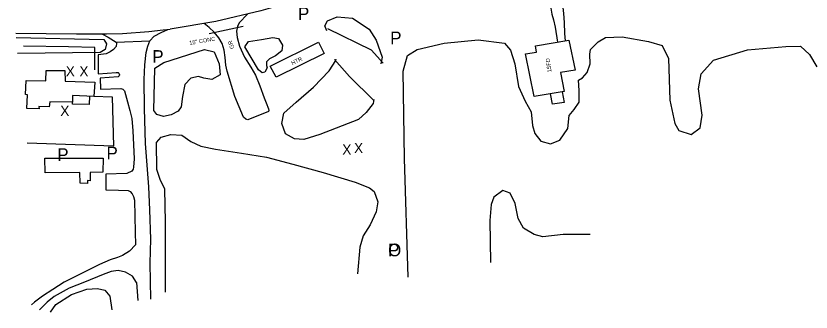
# Model space of a CAD drawing. Extents: x 2030130 to 2036320, y 723205 to 762423.
# Drawn here: x 2031864 to 2032648, y 738991 to 739283 of the extents above; entities that cross this region are included whole.
import ezdxf

# ---------------------------------------------------------------- set-up
doc = ezdxf.new("R2010")
doc.units = 0
for name, color, linetype in [('Draft_Station Cardinal Points', 7, 'Continuous'), ('Draft_Station Labels Major', 7, 'Continuous'), ('Draft_Station Tics Major', 7, 'Continuous'), ('Draft_Station Tics Minor', 7, 'Continuous'), ('Exist Terrain Model Ground Surface', 7, 'Continuous'), ('Old_Level_23', 7, 'Continuous'), ('Old_Level_26', 7, 'Continuous'), ('Old_Level_28', 7, 'Continuous'), ('Prop Horizontal Alignment Ramp', 7, 'Continuous')]:
    doc.layers.add(name, color=color, linetype=linetype)

msp = doc.modelspace()

# ---------------------------------------------------------------- linework, layer by layer
at = {"layer": 'Draft_Station Labels Major'}
for points in [[(2032501.35, 739404.8), (2032453.11, 739391.15), (2032410.68, 739378.56), (2032368.18, 739366.15), (2032325.83, 739353.7), (2032282.45, 739340.8), (2032239.49, 739328.13), (2032193.77, 739314.4), (2032149.21, 739301.07), (2032105.74, 739288.07), (2032061.22, 739277.6), (2032016.41, 739270.14)], [(2032395.37, 739374.09), (2032391, 739368.84), (2032390.01, 739363.89), (2032390.6, 739360.06), (2032392.28, 739351.4), (2032395.19, 739334.2), (2032398.05, 739320.73), (2032402.69, 739297.31), (2032403.83, 739285.39), (2032404.6, 739276.47), (2032405.01, 739265.88), (2032405.71, 739258.6)], [(2032367.63, 739365.99), (2032372.06, 739362.41), (2032375.31, 739359.03), (2032377.7, 739354.49), (2032379.62, 739349.87), (2032381.34, 739344.97), (2032383.76, 739333.66), (2032386.53, 739316.3), (2032388.71, 739302.76), (2032390.1, 739296.11), (2032391.46, 739290.87), (2032392.58, 739284.92), (2032394.01, 739279.2), (2032395.58, 739272.11), (2032398.05, 739257.33)], [(2032092.38, 739284.93), (2032084.38, 739276.17), (2032082.66, 739272.56), (2032081.76, 739268.15), (2032082.18, 739261.93), (2032084.7, 739253.19), (2032089.4, 739242.26), (2032095.86, 739232.53), (2032100.49, 739224.62), (2032104.66, 739214), (2032108.87, 739202.27), (2032110.83, 739197.27), (2032113.11, 739191.47), (2032113.38, 739189.75), (2032113.13, 739188.84), (2032092.81, 739180.45), (2032090.89, 739181.22), (2032088.66, 739183.28), (2032080.13, 739203.44), (2032072.32, 739228.45), (2032071.26, 739234.52), (2032070.53, 739242.04), (2032069.57, 739249.37), (2032067.46, 739256.04), (2032064.15, 739261.63), (2032059.68, 739267.07), (2032054.59, 739271.76), (2032049.88, 739275.71)], [(2031864.24, 739266.19), (2031923.81, 739265.48), (2031953.41, 739265.46), (2031969.19, 739265.78), (2031995.1, 739267.66), (2032009.5, 739269.27), (2032016.41, 739270.14)], [(2031948.98, 739265.46), (2031955.15, 739262.13), (2031963.1, 739257.15), (2031996.15, 739258.68), (2032000.54, 739263.25), (2032007.25, 739266.8), (2032013.99, 739269.84)], [(2031963.1, 739257.15), (2031963.3, 739256.11), (2031962.9, 739253.01), (2031960.49, 739249.84), (2031957.12, 739247.6), (2031953.18, 739245.75), (2031945.2, 739244.64), (2031945.48, 739225.89), (2031963.21, 739227.19), (2031965, 739227.28), (2031965.84, 739226.7), (2031966.28, 739225.05), (2031966.05, 739223.84), (2031965.08, 739222.96), (2031947.26, 739221.63), (2031947.49, 739210.97), (2031967.78, 739211.45), (2031969.63, 739210.86), (2031971.18, 739209.24), (2031974.39, 739198.23), (2031976.64, 739189.69), (2031978.6, 739181.84), (2031979.37, 739169.58), (2031980.8, 739141.96), (2031980.15, 739133.8), (2031979.72, 739131.8), (2031978.39, 739129.76), (2031973.72, 739127.72), (2031952.97, 739126.87), (2031952.86, 739111.42), (2031965.46, 739111.1), (2031974.95, 739110.67), (2031976.85, 739109.7), (2031978.98, 739107.39), (2031980.12, 739105), (2031981.03, 739101.4), (2031981.87, 739069.6), (2031982.03, 739057.22)], [(2031997.19, 739062.85), (2031996.18, 739091.74), (2031995.1, 739114.33), (2031992.08, 739157.34), (2031991.08, 739191.62), (2031990.55, 739220.3), (2031991.22, 739234.85), (2031992.61, 739247.05), (2031994.19, 739253.35), (2031996.15, 739258.68)], [(2031997.13, 739003.43), (2031996.65, 739039.22), (2031997.19, 739062.85)], [(2031982.03, 739057.22), (2031976.3, 739050.91), (2031969.41, 739046.78), (2031964.41, 739044.81), (2031957.1, 739042.25), (2031946.7, 739037.76), (2031927.6, 739028.32), (2031911.93, 739020.23), (2031900.74, 739013.1), (2031890.49, 739006.44), (2031882.64, 739000.61), (2031879.56, 738997.88)], [(2031983.15, 739019.91), (2031979.02, 739026.29), (2031972.42, 739030.19), (2031965.02, 739031.74), (2031957.99, 739030.8), (2031950.23, 739027.85), (2031931.89, 739020.34), (2031916.76, 739014.49), (2031901.85, 739006), (2031895.02, 739000.68), (2031887.56, 738993.08)], [(2031983.15, 739019.91), (2031984.27, 739002.12)]]:
    msp.add_lwpolyline(points, dxfattribs=at)
at = {"layer": 'Draft_Station Tics Major'}
for points in [[(2032170.6, 739268.5), (2032168.68, 739273.37), (2032171.41, 739278.3), (2032180.82, 739282.2), (2032196.12, 739280.91), (2032212.52, 739270.13), (2032219.42, 739259.27), (2032225.38, 739242.56), (2032224.03, 739235.75)], [(2032226.31, 739236.33), (2032214.71, 739249.21), (2032171.52, 739270.46)], [(2031864.47, 739261.67), (2031950.88, 739259.96), (2031953.38, 739255.67), (2031952.12, 739250.11), (2031947.27, 739246.98), (2031865.95, 739246.04)], [(2032103.48, 739229.91), (2032089.85, 739252.73), (2032093.46, 739257.99), (2032106.15, 739259.74), (2032117.51, 739261.77), (2032123.11, 739260.93), (2032127.1, 739254.39), (2032126.26, 739248.79), (2032120.2, 739243.58), (2032114.02, 739240.74), (2032111.13, 739237.78), (2032111.14, 739234.14), (2032112.04, 739231.86), (2032109.46, 739227.6), (2032107.11, 739226.88), (2032103.48, 739229.91)], [(2032250.76, 739025.35), (2032247.33, 739142.36), (2032246.07, 739228.6), (2032250.08, 739244.16), (2032259.75, 739249.99), (2032286.48, 739256.24), (2032319.7, 739259.36), (2032345.67, 739256.2), (2032351.59, 739249.4), (2032355.89, 739235.89), (2032359.46, 739213.38), (2032366.31, 739199.05), (2032372.13, 739188.37), (2032373.38, 739174.87), (2032375.82, 739167.12), (2032381.48, 739159.41), (2032391.17, 739156.94), (2032400.3, 739160.53), (2032408.11, 739172.11), (2032409.66, 739184.67), (2032414.42, 739190.6), (2032419.41, 739198.03), (2032419.33, 739209.55), (2032418.8, 739219.68), (2032422.56, 739221.97), (2032427.43, 739227.12), (2032430.07, 739235.86), (2032429.99, 739245.36), (2032430.65, 739249.87), (2032438.12, 739257.67), (2032445.43, 739261.76), (2032461.76, 739262.5)], [(2032461.76, 739262.5), (2032487.84, 739257.96), (2032501.1, 739253.86), (2032507.48, 739241.06), (2032508.59, 739199.88), (2032513.68, 739176.93), (2032517.51, 739170.17), (2032529.76, 739166.08), (2032538.8, 739172.81), (2032540.7, 739185.01), (2032536.93, 739211.29), (2032539.72, 739225.84), (2032551.76, 739239.36), (2032585.2, 739249.53), (2032623.06, 739252.98), (2032637.47, 739253.15), (2032646.4, 739245.16), (2032653.59, 739232.87)], [(2032000.05, 739189.87), (2032001.14, 739231.44), (2032010.04, 739237.16), (2032050.05, 739249.85), (2032059.77, 739247.79), (2032064.64, 739235.93), (2032065.45, 739225.1), (2032057.4, 739220.31), (2032049.56, 739221.69), (2032044.11, 739223.19), (2032036.6, 739221.66), (2032030.89, 739215.57), (2032028.54, 739203.5), (2032027.04, 739193.38), (2032024.29, 739189.06), (2032017.43, 739185.35), (2032009.68, 739183.93), (2032003.08, 739185.79), (2032000.05, 739189.87)], [(2032163.66, 739166.01), (2032148.15, 739161.13), (2032138.97, 739161.78), (2032129.93, 739166.74), (2032126.35, 739176.88), (2032128.44, 739187.03), (2032140.35, 739197.99), (2032157.49, 739212.63), (2032172.83, 739228.79), (2032179.51, 739239.12), (2032179.78, 739240.41)], [(2032178.13, 739240.03), (2032192.95, 739223.28), (2032216.64, 739200.09)], [(2032217.05, 739200.5), (2032216.28, 739196.62), (2032209.57, 739187.91), (2032202, 739180.88), (2032163.66, 739166.01)], [(2032011.52, 739010.37), (2032011.55, 739079.9), (2032011.11, 739111.95), (2032006.54, 739121.51), (2032003.21, 739131.54), (2032002.7, 739158.1), (2032007.5, 739163.43), (2032017.04, 739165.96), (2032027.76, 739165.51), (2032036.58, 739159.05), (2032046.6, 739154.68), (2032061.05, 739151.44), (2032086.63, 739147.71), (2032111.16, 739143.57), (2032137.08, 739136.94), (2032167.15, 739128.49), (2032198.48, 739118.91), (2032212.8, 739113.4), (2032217.47, 739109.76), (2032221.06, 739099.62), (2032219.31, 739089.61), (2032213.42, 739076.76), (2032206.53, 739065.94), (2032203.17, 739054.89), (2032200.8, 739028.43)], [(2032430.07, 739067.24), (2032403.49, 739067.33), (2032383.54, 739064.97), (2032374.87, 739067.44), (2032364.51, 739073.7), (2032359.17, 739083.15), (2032356.25, 739097.81), (2032351.33, 739108.24), (2032344.27, 739110.74), (2032335.23, 739104.35), (2032332.63, 739097.04), (2032331.21, 739081.08), (2032332.01, 739039.85)], [(2031898.19, 738990.74), (2031903.7, 738998.38), (2031919.14, 739008.1), (2031934.02, 739013.54), (2031944.5, 739014.22), (2031951.88, 739012.46), (2031956.93, 739006.33), (2031958.77, 738992.87)]]:
    msp.add_lwpolyline(points, dxfattribs=at)
at = {"layer": 'Draft_Station Tics Minor'}
msp.add_lwpolyline([(2032088.26, 739272.68), (2032054.79, 739265.51)], dxfattribs=at)
at = {"layer": 'Exist Terrain Model Ground Surface'}
for points in [[(2032168.04, 739246.15), (2032120.7, 739222.68), (2032114.93, 739233.49), (2032162.62, 739257.09)], [(2032415.34, 739229.53), (2032401.03, 739227.25), (2032404.53, 739208.55), (2032375.03, 739203.65), (2032366.42, 739245.68), (2032377.36, 739247.24), (2032376.24, 739253.7), (2032409.35, 739259.21)], [(2031874.31, 739219.52), (2031893.72, 739219.14), (2031894.12, 739229.23), (2031912.62, 739229.1), (2031912.83, 739218.75), (2031942.14, 739217.69), (2031941.14, 739203.72), (2031920.16, 739204.49), (2031919.91, 739197.91), (2031897.63, 739198.37), (2031897.14, 739193.42), (2031886.96, 739193.78), (2031887.18, 739191.43), (2031875.09, 739191.75), (2031875.58, 739205.22), (2031873.62, 739205.56)], [(2031892.79, 739142.85), (2031950.13, 739142.68), (2031949.99, 739128.84), (2031937.47, 739128.48), (2031937.47, 739120.47), (2031934.69, 739120.59), (2031934.95, 739117.86), (2031927.71, 739117.95), (2031927.34, 739128.45), (2031892.93, 739128.31)]]:
    msp.add_lwpolyline(points, close=True, dxfattribs=at)
for points in [[(2031942.14, 739229.77), (2031942.14, 739251.97), (2031916.11, 739252.69), (2031871.84, 739253.13)], [(2031941.16, 739203.91), (2031959.22, 739203.34), (2031960.36, 739154.53), (2031875.4, 739157.42)], [(2031936.67, 739203.88), (2031936.52, 739195.62), (2031919.92, 739196.09), (2031919.91, 739197.91)], [(2032402.76, 739208.26), (2032404.74, 739197.69), (2032393.19, 739195.88), (2032391.09, 739206.32)]]:
    msp.add_lwpolyline(points, dxfattribs=at)

# ---------------------------------------------------------------- texts
at = {"layer": 'Draft_Station Cardinal Points'}
msp.add_text('O', height=12.5, dxfattribs=at).set_placement((2032231.06, 739045.83))
at = {"layer": 'Draft_Station Tics Major'}
for p in [(2031913.43, 739223.44), (2031926.82, 739223.43), (2031907.99, 739184.41), (2032185.96, 739146.21), (2032197.53, 739147.71)]:
    msp.add_text('X', height=10, dxfattribs=at).set_placement(p)
at = {"layer": 'Old_Level_23'}
msp.add_text('GR', height=4, rotation=107.88847, dxfattribs=at).set_placement((2032079.53, 739251.28))
at = {"layer": 'Old_Level_26'}
msp.add_text('15" CONC', height=4, rotation=9.6322, dxfattribs=at).set_placement((2032035.49, 739254.44))
at = {"layer": 'Old_Level_28'}
for s, rotation, p in [('HTR', 25.80827, (2032136.78, 739234.4)), ('1SFD', 97.8704, (2032392.18, 739227.6))]:
    msp.add_text(s, height=4, rotation=rotation, dxfattribs=at).set_placement(p)
at = {"layer": 'Prop Horizontal Alignment Ramp'}
for p in [(2032142.25, 739279.14), (2032233.13, 739255.15), (2031998.66, 739236.82), (2031953.5, 739141.52), (2031904.96, 739139.97), (2032231.06, 739045.83)]:
    msp.add_text('P', height=12.5, dxfattribs=at).set_placement(p)

doc.saveas('drawing.dxf')
